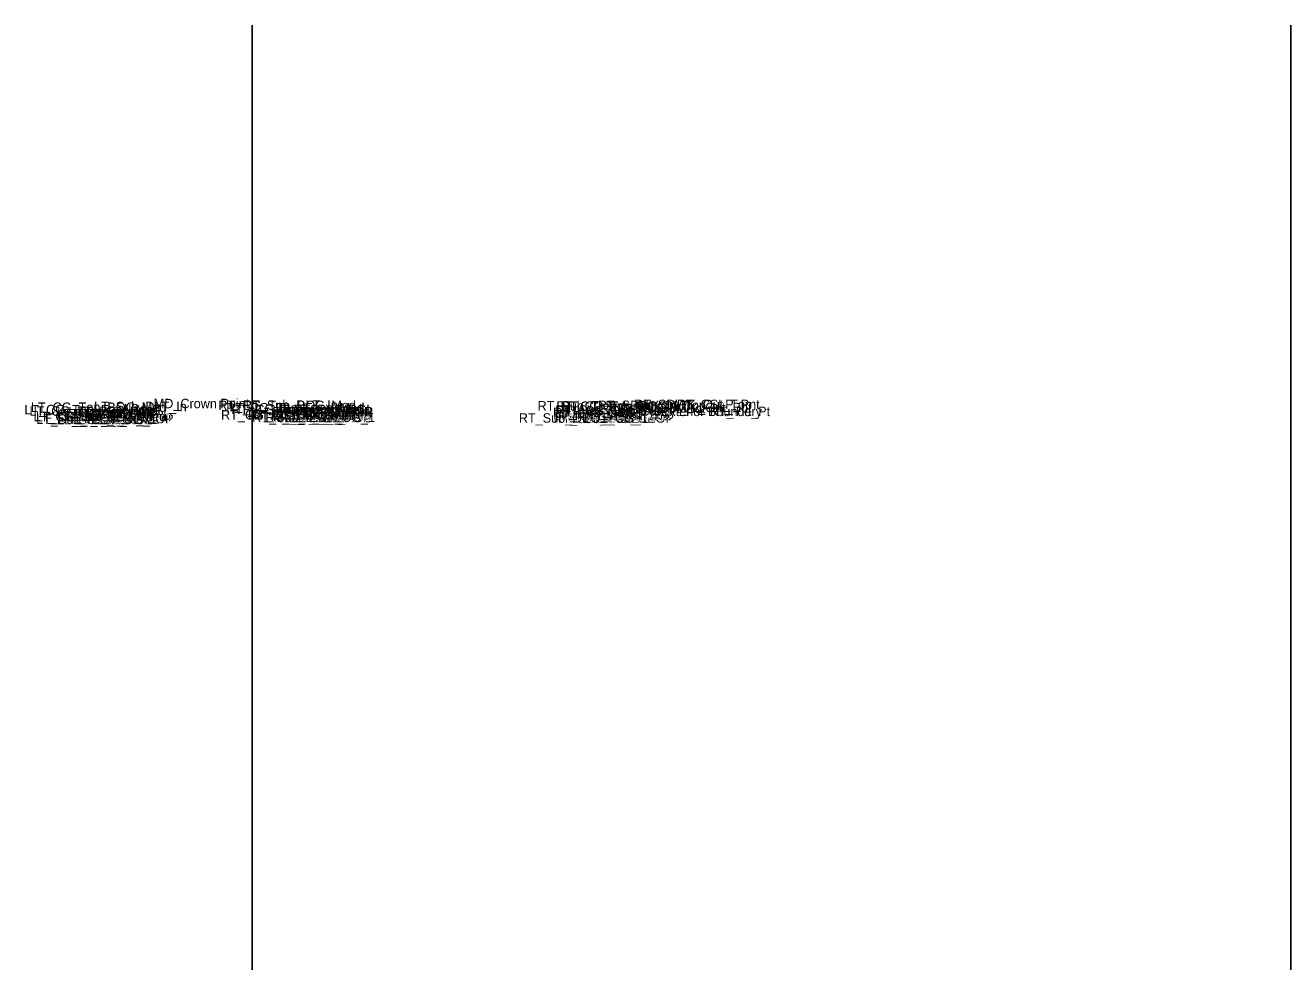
# Model space of a CAD drawing. Extents: x 0 to 6300, y -50 to 9550.
# Drawn here: x 2126 to 2260, y 7450 to 7550 of the extents above; entities that cross this region are included whole.
import ezdxf

# ---------------------------------------------------------------- set-up
doc = ezdxf.new("R2010")
doc.units = 0
for name, color, linetype in [('Default', 7, 'Continuous'), ('Prop XS Exc Vertical Line 2', 7, 'Continuous'), ('Prop XS Exc Vertical Line 3', 7, 'Continuous')]:
    doc.layers.add(name, color=color, linetype=linetype)

msp = doc.modelspace()

# ---------------------------------------------------------------- linework, layer by layer
at = {"layer": 'Prop XS Exc Vertical Line 2'}
msp.add_line((2150, 7550), (2150, 7450), dxfattribs=at)
at = {"layer": 'Prop XS Exc Vertical Line 3'}
msp.add_line((2260, 7550), (2260, 7450), dxfattribs=at)

# ---------------------------------------------------------------- texts
at = {"layer": 'Default'}
for s, p in [('LT_CG_Top_Face_Med', (2125.87, 7508.81)), ('LT_CG_Top_Gut_Med', (2126.42, 7508.65)), ('LT_CG_Top_BOC_Med', (2126.57, 7509.06)), ('LT_PV2_OEEOP', (2129.29, 7508.38)), ('LT_PV2_IEEOP', (2130.05, 7508.38)), ('LT_PV2_PGL', (2131.26, 7508.38)), ('LT_PV1_PGL', (2131.5, 7508.63)), ('LT_Sub_DLT_In', (2133.26, 7509.14)), ('MD_Crown Point', (2139.58, 7509.45)), ('RT_CG_Top_BOC_Med', (2146.43, 7509.25)), ('RT_CG_Top_Face_Med', (2147.25, 7509)), ('RT_CG_Top_Gut_Med', (2147.8, 7508.83)), ('RT_Sub_DLT_In', (2149.04, 7509.29)), ('RT_PV2_OEEOP', (2152.17, 7508.58)), ('RT_PV2_IEEOP', (2152.93, 7508.58)), ('RT_PV2_PGL', (2154.15, 7508.58)), ('RT_PV1_PGL', (2154.38, 7508.83)), ('RT_Sub_Trench_Out_DLT', (2180.23, 7509.21)), ('RT_PV2_OEOT', (2181.87, 7508.51)), ('RT_PV1_OEOT', (2182.11, 7508.76)), ('RT_CG_Top_Face', (2182.22, 7509.17)), ('RT_CG_Top_BOC', (2182.69, 7509.17)), ('RT_CG_Top_Gut', (2182.75, 7508.67)), ('RT_SDWK_In_Top', (2186.62, 7509.26)), ('RT_SDWK_In_Bot', (2186.87, 7508.93)), ('RT_SDWK_Out_Top', (2190.46, 7509.36)), ('RT_SDWK_Out_Bot', (2190.71, 7509.03)), ('Exterior Boundary', (2193.3, 7508.62)), ('RT_CSLP_Pnt', (2194.98, 7509.36)), ('RT_Tie_Pt', (2198.47, 7508.62)), ('LT_CG_Bot_BOC_Med', (2126.85, 7508.08)), ('LT_CG_Bot_IE_Med', (2127.09, 7508.05)), ('LT_Sub_IEOT_CG_1', (2127.13, 7507.8)), ('LT_PV3_OEEOP', (2129.29, 7508.13)), ('LT_Sub_OEEOP', (2129.33, 7507.76)), ('LT_Sub_IEEOP', (2130.09, 7507.76)), ('LT_CG1_Shelf_In', (2130.71, 7508.09)), ('LT_Sub_PGL', (2131.31, 7507.76)), ('LT_Sub_IEOP', (2133.05, 7507.84)), ('RT_CG_Bot_BOC_Med', (2146.71, 7508.25)), ('RT_CG1_Shelf_In', (2149.57, 7508.25)), ('RT_CG_Bot_IE_Med', (2149.98, 7508.25)), ('RT_Sub_IEOT_CG_1', (2150.01, 7508)), ('RT_Sub_IEOP', (2151.41, 7508.01)), ('RT_PV3_OEEOP', (2152.17, 7508.33)), ('RT_Sub_OEEOP', (2152.21, 7507.96)), ('RT_Sub_IEEOP', (2152.97, 7507.96)), ('RT_Sub_PGL', (2154.19, 7507.96)), ('RT_Sub_OEOT_CG_1', (2178.25, 7507.92)), ('RT_PV3_OEOT', (2181.87, 7508.26)), ('RT_Sub_OEOT', (2181.92, 7507.88)), ('RT_CG_Bot_IE', (2182.22, 7508.17)), ('RT_CG1_Shelf_Out', (2182.36, 7508.17)), ('RT_CG_Bot_BOC', (2182.97, 7508.17)), ('RT_Sub_OEOP', (2185.16, 7507.92))]:
    msp.add_text(s, height=1, dxfattribs=at).set_placement(p)

doc.saveas('drawing.dxf')
